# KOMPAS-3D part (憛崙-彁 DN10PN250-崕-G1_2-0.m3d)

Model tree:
1. Объединить компоненты:1  (labels: СЕНС-ПР DN10PN250-НО-G1/2-0)

Referenced files in D:\Савин\!СЕНСОР\3D для заказчика\!Новый перечень\СЕНС-ПР\6. СЕНС-ПР-PN250-НО\DN10\: СЕНС-ПР DN10PN250-НО-G1_2-0.a3d
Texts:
  СЕНС-ПР DN10PN250-НО-G1/2-0
  ООО НПП Сенсор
